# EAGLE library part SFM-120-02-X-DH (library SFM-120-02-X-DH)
0.050"X0.050" SOCKET STRIP ASSEMBLY.
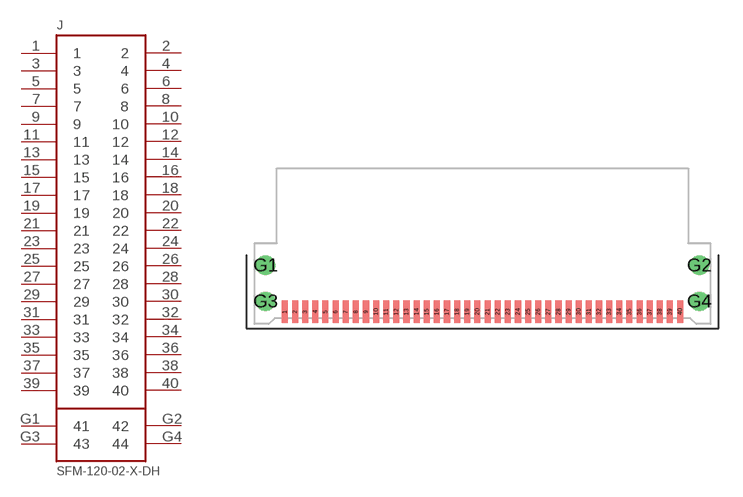
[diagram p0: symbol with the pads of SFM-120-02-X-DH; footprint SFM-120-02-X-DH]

Designator prefix J

## SFM-120-02-X-DH  [SFM-120-02-X-DH]
1  1
2  2
3  3
4  4
5  5
6  6
7  7
8  8
9  9
10  10
11  11
12  12
13  13
14  14
15  15
16  16
17  17
18  18
19  19
20  20
21  21
22  22
23  23
24  24
25  25
26  26
27  27
28  28
29  29
30  30
31  31
32  32
33  33
34  34
35  35
36  36
37  37
38  38
39  39
40  40
G1  41
G2  42
G3  43
G4  44

## Footprint SFM-120-02-X-DH (pad centres in mm)
0.050"X0.050" SOCKET STRIP ASSEMBLY.
smd 0.381 x 1.397: 1 -12.383,-4.051; 2 -11.748,-4.051; 3 -11.113,-4.051; 4 -10.477,-4.051; 5 -9.842,-4.051; 6 -9.207,-4.051; 7 -8.572,-4.051; 8 -7.938,-4.051; 9 -7.303,-4.051; 10 -6.668,-4.051; 11 -6.032,-4.051; 12 -5.397,-4.051; 13 -4.763,-4.051; 14 -4.128,-4.051; 15 -3.493,-4.051; 16 -2.857,-4.051; 17 -2.223,-4.051; 18 -1.587,-4.051; 19 -0.953,-4.051; 20 -0.318,-4.051; 21 0.318,-4.051; 22 0.953,-4.051; 23 1.587,-4.051; 24 2.223,-4.051; 25 2.857,-4.051; 26 3.493,-4.051; 27 4.128,-4.051; 28 4.763,-4.051; 29 5.397,-4.051; 30 6.032,-4.051; 31 6.668,-4.051; 32 7.303,-4.051; 33 7.938,-4.051; 34 8.572,-4.051; 35 9.207,-4.051; 36 9.842,-4.051; 37 10.477,-4.051; 38 11.113,-4.051; 39 11.748,-4.051; 40 12.383,-4.051
drill 0.711 pad 1.143 round: G1 -13.589,-1.143; G2 13.589,-1.143; G3 -13.589,-3.404; G4 13.589,-3.404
